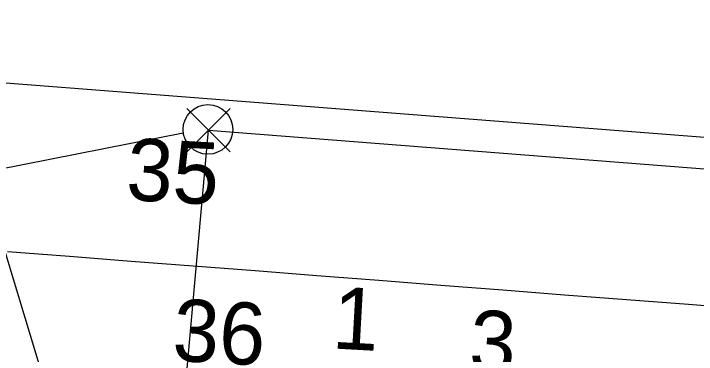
# Model space of a CAD drawing. Extents: x -669661 to -669105, y -977202 to -977030.
# Drawn here: x -669522.3 to -669511.31, y -977138.36 to -977132.88 of the extents above; entities that cross this region are included whole.
import ezdxf

# ---------------------------------------------------------------- set-up
doc = ezdxf.new("R2010")
doc.units = 0
for name, color, linetype in [('elektro-EOV', 7, 'Continuous'), ('elektro-osvetleni', 7, 'Continuous'), ('KOL_osy', 7, 'Continuous'), ('ODV_trativody_potrubí', 7, 'Continuous'), ('SO 01-86-01_vytyč_body', 7, 'Continuous'), ('SO 11-12-01_vytyč_body', 7, 'Continuous')]:
    doc.layers.add(name, color=color, linetype=linetype)

# ---------------------------------------------------------------- blocks, each defined once
blk = doc.blocks.new('POINT_DISPLAY')
for p, q in [((-0.35, -0.35), (0.35, 0.35)), ((-0.35, 0.35), (0.35, -0.35))]:
    blk.add_line(p, q)

msp = doc.modelspace()

# ---------------------------------------------------------------- linework, layer by layer
at = {"layer": 'elektro-EOV'}
for p, q in [((-669522.827, -977135.436), (-669519.569, -977134.797)), ((-669520.178, -977144.14), (-669522.827, -977135.436))]:
    msp.add_line(p, q, dxfattribs=at)
at = {"layer": 'elektro-osvetleni'}
msp.add_lwpolyline([(-669520.014, -977144.295), (-669519.163, -977134.751), (-669492.657, -977136.821), (-669476.036, -977138.048), (-669457.361, -977138.783)], dxfattribs=at)
msp.add_circle((-669519.171, -977134.741), 0.4, dxfattribs=at)
at = {"layer": 'KOL_osy'}
msp.add_lwpolyline([(-669522.401, -977136.706), (-669521.404, -977136.783), (-669520.407, -977136.861), (-669519.41, -977136.939), (-669518.413, -977137.016), (-669517.416, -977137.094), (-669516.419, -977137.171), (-669515.422, -977137.249), (-669514.425, -977137.327), (-669513.428, -977137.404), (-669512.431, -977137.482), (-669511.434, -977137.559), (-669510.437, -977137.637)], dxfattribs=at)
at = {"layer": 'ODV_trativody_potrubí'}
msp.add_lwpolyline([(-669495.771, -977136.07), (-669530.167, -977133.393), (-669554.095, -977131.53), (-669570.744, -977128.591)], dxfattribs=at)

# ---------------------------------------------------------------- block references
at = {"layer": 'SO 01-86-01_vytyč_body'}
msp.add_blockref('POINT_DISPLAY', (-669519.163, -977134.751), dxfattribs=at)

# ---------------------------------------------------------------- texts
msp.add_text('35', height=1, rotation=356.8465, dxfattribs=at).set_placement((-669520.503, -977135.875))
at = {"layer": 'SO 11-12-01_vytyč_body'}
for s, p in [('1', (-669517.184, -977138.269)), ('36', (-669519.757, -977138.465)), ('3', (-669514.979, -977138.642))]:
    msp.add_text(s, height=1, rotation=356.8465, dxfattribs=at).set_placement(p)

doc.saveas('drawing.dxf')
